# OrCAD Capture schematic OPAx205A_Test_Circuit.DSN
size A; title: OPA2205 2-µV, 0.04-µV/°C, Low-Power, Super Beta, Bipolar, e-; rev: 1.1; note: Datasheet: SBOS962B   EVM: N/A
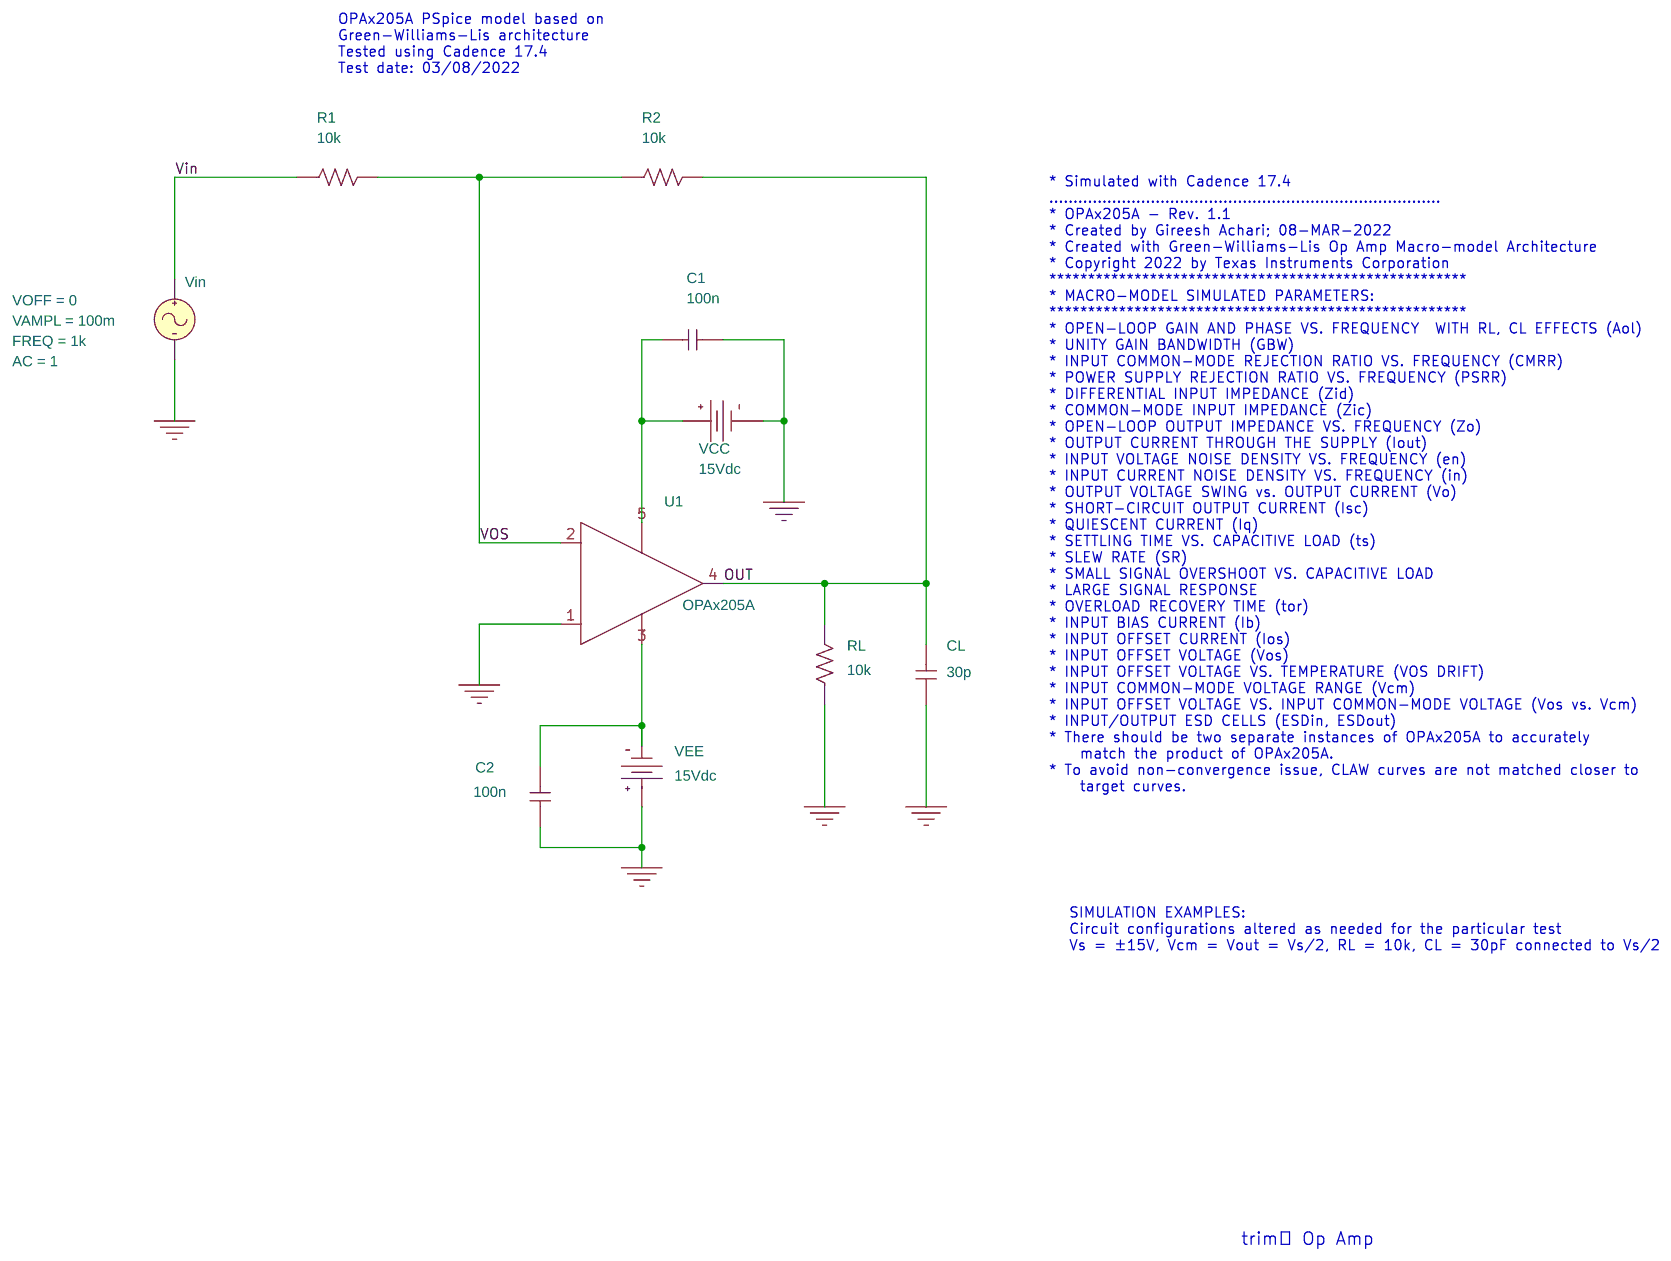
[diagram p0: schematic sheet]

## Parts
C1  100n  [cap196]
C2  100n  [cap196]
CL  30p  [cap196]
R1  10k  [AXRC05]
R2  10k  [AXRC05]
RL  10k  [AXRC05]
U1  OPAx205A
VCC  VDC
VEE  VDC
Vin  VSIN

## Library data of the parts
C1 C2 CL = C
R1 R2 RL = R
U1 = OPAx205A
VCC VEE = VDC: DC: 15Vdc
Vin = VSIN: AC: 1; FREQ: 1k; VAMPL: 100m; VOFF: 0

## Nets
Vin: R1.1 Vin.1(+)
0: C1.2 C2.1 CL.2 RL.1 U1.1(+) VCC.1(-) VEE.0(+) Vin.2(-)
OUT: CL.1 R2.2 RL.2 U1.4(OUT)
VOS: R1.2 R2.1 U1.2(-)
N27303: C1.1 U1.5(V+) VCC.0(+)
N27354: C2.2 U1.3(V-) VEE.1(-)

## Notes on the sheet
- OPAx205A PSpice model based on
  Green-Williams-Lis architecture
  Tested using Cadence 17.4
  Test date: 03/08/2022
- * Simulated with Cadence 17.4
  .................................................................................
  * OPAx205A - Rev. 1.1
  * Created by Gireesh Achari; 08-MAR-2022
  * Created with Green-Williams-Lis Op Amp Macro-model Architecture
  * Copyright 2022 by Texas Instruments Corporation
  ******************************************************
  * MACRO-MODEL SIMULATED PARAMETERS:
  ******************************************************
  * OPEN-LOOP GAIN AND PHASE VS. FREQUENCY  WITH RL, CL EFFECTS (Aol)
  * UNITY GAIN BANDWIDTH (GBW)
  * INPUT COMMON-MODE REJECTION RATIO VS. FREQUENCY (CMRR)
  * POWER SUPPLY REJECTION RATIO VS. FREQUENCY (PSRR)
  * DIFFERENTIAL INPUT IMPEDANCE (Zid)
  * COMMON-MODE INPUT IMPEDANCE (Zic)
  * OPEN-LOOP OUTPUT IMPEDANCE VS. FREQUENCY (Zo)
  * OUTPUT CURRENT THROUGH THE SUPPLY (Iout)
  * INPUT VOLTAGE NOISE DENSITY VS. FREQUENCY (en)
  * INPUT CURRENT NOISE DENSITY VS. FREQUENCY (in)
  * OUTPUT VOLTAGE SWING vs. OUTPUT CURRENT (Vo)
  * SHORT-CIRCUIT OUTPUT CURRENT (Isc)
  * QUIESCENT CURRENT (Iq)
  * SETTLING TIME VS. CAPACITIVE LOAD (ts)
  * SLEW RATE (SR)
  * SMALL SIGNAL OVERSHOOT VS. CAPACITIVE LOAD
  * LARGE SIGNAL RESPONSE
  * OVERLOAD RECOVERY TIME (tor)
  * INPUT BIAS CURRENT (Ib)
  * INPUT OFFSET CURRENT (Ios)
  * INPUT OFFSET VOLTAGE (Vos)
  * INPUT OFFSET VOLTAGE VS. TEMPERATURE (VOS DRIFT)
  * INPUT COMMON-MODE VOLTAGE RANGE (Vcm)
  * INPUT OFFSET VOLTAGE VS. INPUT COMMON-MODE VOLTAGE (Vos vs. Vcm)
  * INPUT/OUTPUT ESD CELLS (ESDin, ESDout)
  * There should be two separate instances of OPAx205A to accurately
      match the product of OPAx205A.
  * To avoid non-convergence issue, CLAW curves are not matched closer to
      target curves.
- SIMULATION EXAMPLES:
  Circuit configurations altered as needed for the particular test
  Vs = ±15V, Vcm = Vout = Vs/2, RL = 10k, CL = 30pF connected to Vs/2
- trim™ Op Amp
